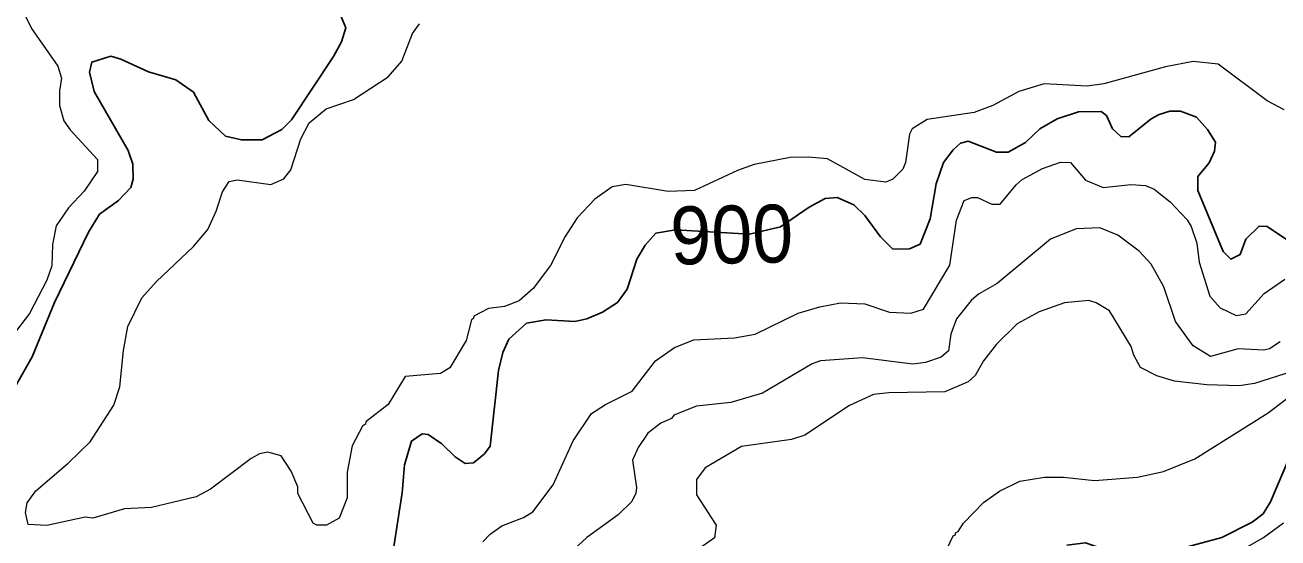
# Model space of a CAD drawing. Extents: x 598.3 to 623.2, y 6902.2 to 6930.1.
# Drawn here: x 617.225 to 618.956, y 6915.484 to 6916.193 of the extents above; entities that cross this region are included whole.
import ezdxf
from ezdxf.enums import TextEntityAlignment as Align

# ---------------------------------------------------------------- set-up
doc = ezdxf.new("R2010")
doc.units = 0
doc.header["$LTSCALE"] = 0.032
doc.layers.add('1', color=7, linetype='Continuous', lineweight=25)
doc.layers.add('2', color=7, linetype='Continuous', lineweight=13)
doc.layers.add('61', color=7, linetype='Continuous')

msp = doc.modelspace()

# ---------------------------------------------------------------- linework, layer by layer
at = {"layer": '1'}
for points in [[(617.2112, 6915.6929), (617.2344, 6915.7347), (617.2654, 6915.8095), (617.3126, 6915.907), (617.3277, 6915.9319), (617.3538, 6915.9509), (617.3711, 6915.9685), (617.3742, 6915.9802), (617.3738, 6916.0009), (617.3674, 6916.0197), (617.3202, 6916.1013), (617.3137, 6916.1281), (617.3172, 6916.1421), (617.3434, 6916.1501), (617.3569, 6916.1463), (617.3952, 6916.1288), (617.4333, 6916.1177), (617.4577, 6916.1005), (617.4785, 6916.0614), (617.5019, 6916.0394), (617.5237, 6916.0344), (617.5523, 6916.0344), (617.5796, 6916.0488), (617.5929, 6916.0621), (617.6509, 6916.1499), (617.6619, 6916.1702), (617.6679, 6916.1892), (617.6541, 6916.2225)], [(618.9716, 6915.8938), (618.9408, 6915.9147), (618.9296, 6915.9153), (618.9111, 6915.897), (618.9032, 6915.8759), (618.8907, 6915.8695), (618.8797, 6915.88), (618.8451, 6915.9643), (618.8451, 6915.9839), (618.8604, 6916.0028), (618.8677, 6916.0191), (618.8692, 6916.0313), (618.8582, 6916.0487), (618.843, 6916.066), (618.8208, 6916.074), (618.8062, 6916.074), (618.7914, 6916.0698), (618.7806, 6916.0637), (618.7494, 6916.0385), (618.7385, 6916.0393), (618.7269, 6916.0498), (618.7187, 6916.0683), (618.7112, 6916.0737), (618.68, 6916.0732), (618.6506, 6916.0634), (618.6265, 6916.0497), (618.6068, 6916.0307), (618.5828, 6916.0174), (618.5666, 6916.0174), (618.5275, 6916.0326), (618.5171, 6916.0299), (618.5071, 6916.0209), (618.4937, 6916.003), (618.4833, 6915.9739), (618.4752, 6915.9254), (618.4612, 6915.8903), (618.4468, 6915.8839), (618.4234, 6915.8836), (618.4065, 6915.9005), (618.3847, 6915.9297), (618.3697, 6915.9446), (618.3467, 6915.9549), (618.3303, 6915.9534), (618.308, 6915.9416), (618.2684, 6915.9142), (618.2256, 6915.9041), (618.1232, 6915.9102), (618.0963, 6915.9054), (618.0813, 6915.8891), (618.0701, 6915.8694), (618.0567, 6915.8282), (618.0431, 6915.8097), (618.0224, 6915.7962), (618.0008, 6915.7869), (617.9841, 6915.7835), (617.9446, 6915.7858), (617.9177, 6915.7811), (617.8932, 6915.7591), (617.8848, 6915.7406), (617.8789, 6915.7154), (617.8673, 6915.6108), (617.8596, 6915.6004), (617.8443, 6915.588), (617.8327, 6915.5868), (617.8188, 6915.5962), (617.8006, 6915.6144), (617.7817, 6915.6269), (617.7734, 6915.6279), (617.7588, 6915.6181), (617.7491, 6915.5854), (617.7458, 6915.5465), (617.7337, 6915.4688)], [(618.6637, 6915.4742), (618.6896, 6915.4774), (618.7217, 6915.4662), (618.7616, 6915.4605), (618.7997, 6915.4636), (618.8782, 6915.4846), (618.9198, 6915.5059), (618.9351, 6915.5174), (618.9453, 6915.5338), (618.9809, 6915.6173)]]:
    msp.add_lwpolyline(points, dxfattribs=at)
at = {"layer": '2'}
for points in [[(617.2245, 6916.2072), (617.2335, 6916.1887), (617.2702, 6916.1362), (617.2753, 6916.1198), (617.2723, 6916.1021), (617.2723, 6916.0819), (617.2785, 6916.0608), (617.2873, 6916.0485), (617.3248, 6916.0073), (617.3248, 6915.9909), (617.3064, 6915.9634), (617.2848, 6915.9407), (617.268, 6915.9156), (617.2626, 6915.89), (617.2617, 6915.8604), (617.2551, 6915.8407), (617.231, 6915.7946), (617.2084, 6915.7651)], [(617.3607, 6915.7431), (617.367, 6915.7764), (617.3862, 6915.8163), (617.4062, 6915.8387), (617.4575, 6915.8871), (617.4772, 6915.9108), (617.4889, 6915.9358), (617.4974, 6915.9626), (617.5069, 6915.9768), (617.5178, 6915.9793), (617.5644, 6915.9729), (617.5824, 6915.9804), (617.5921, 6915.9929), (617.6058, 6916.0359), (617.6172, 6916.058), (617.6406, 6916.0772), (617.6784, 6916.0905), (617.7263, 6916.1218), (617.7455, 6916.1433), (617.76, 6916.1815), (617.7696, 6916.195)], [(618.9642, 6916.0761), (618.9406, 6916.0885), (618.8729, 6916.1393), (618.8383, 6916.1428), (618.8, 6916.1356), (618.7152, 6916.112), (618.6919, 6916.1089), (618.6324, 6916.1119), (618.5974, 6916.1015), (618.5615, 6916.082), (618.5361, 6916.0724), (618.471, 6916.0626), (618.4503, 6916.0499), (618.4466, 6916.0426), (618.4411, 6916.0031), (618.4372, 6915.9941), (618.4235, 6915.9803), (618.4141, 6915.9762), (618.3847, 6915.9796), (618.3335, 6916.0084), (618.3065, 6916.0108), (618.2816, 6916.01), (618.2321, 6916.0005), (618.2088, 6915.9922), (618.1494, 6915.9646), (618.1131, 6915.9633), (618.0545, 6915.9728), (618.0359, 6915.9695), (618.0119, 6915.9524), (617.9877, 6915.9265), (617.9708, 6915.9008), (617.9507, 6915.8609), (617.9266, 6915.8291), (617.9074, 6915.8118), (617.8871, 6915.8041), (617.8649, 6915.8012), (617.8447, 6915.7907), (617.8444, 6915.7875), (617.8414, 6915.7857), (617.8343, 6915.7572), (617.8118, 6915.7192), (617.7989, 6915.7113), (617.7497, 6915.7071), (617.7263, 6915.6684), (617.6956, 6915.6448), (617.6953, 6915.6416), (617.6909, 6915.6386), (617.6766, 6915.6115), (617.6697, 6915.5751), (617.6696, 6915.5397), (617.6586, 6915.5113), (617.6412, 6915.5017), (617.628, 6915.5018), (617.6228, 6915.5043), (617.6017, 6915.5457), (617.6016, 6915.5546), (617.5926, 6915.5765), (617.5784, 6915.5978), (617.5603, 6915.6028), (617.5485, 6915.6004), (617.5372, 6915.5941), (617.4812, 6915.5514), (617.4614, 6915.5408), (617.3995, 6915.5262), (617.3621, 6915.5243), (617.3186, 6915.5115), (617.3078, 6915.513), (617.2548, 6915.5011), (617.2292, 6915.5025), (617.2252, 6915.5191), (617.2279, 6915.5324), (617.2397, 6915.5492), (617.2844, 6915.5875), (617.3147, 6915.617), (617.3475, 6915.6676), (617.3555, 6915.6929), (617.3607, 6915.7431)], [(618.2334, 6915.7657), (618.293, 6915.7947), (618.3227, 6915.8038), (618.3511, 6915.8093), (618.3848, 6915.8078), (618.4191, 6915.7964), (618.4482, 6915.7947), (618.4657, 6915.8004), (618.5023, 6915.8611), (618.5116, 6915.9237), (618.5222, 6915.9508), (618.5326, 6915.955), (618.5405, 6915.955), (618.5602, 6915.9454), (618.5718, 6915.9454), (618.5938, 6915.9724), (618.6024, 6915.9795), (618.6303, 6915.9949), (618.6554, 6916.0035), (618.6692, 6916.0034), (618.6897, 6915.9787), (618.7139, 6915.9688), (618.7523, 6915.9728), (618.7725, 6915.9712), (618.7844, 6915.9663), (618.8067, 6915.9489), (618.83, 6915.9239), (618.8357, 6915.9145), (618.8433, 6915.8917), (618.8466, 6915.8655), (618.8613, 6915.8185), (618.8759, 6915.8023), (618.8978, 6915.7916), (618.9114, 6915.794), (618.9365, 6915.8219), (618.9649, 6915.8418)], [(618.9586, 6915.7552), (618.9438, 6915.7454), (618.936, 6915.7438), (618.9007, 6915.7454), (618.8622, 6915.735), (618.8383, 6915.7497), (618.8141, 6915.7832), (618.798, 6915.8315), (618.7803, 6915.8627), (618.7639, 6915.8807), (618.7345, 6915.9027), (618.7095, 6915.9129), (618.677, 6915.9114), (618.6415, 6915.897), (618.5676, 6915.8357), (618.5418, 6915.8213), (618.5317, 6915.8125), (618.5114, 6915.7872), (618.5036, 6915.7658), (618.5004, 6915.7426), (618.4904, 6915.7341), (618.4686, 6915.7265), (618.451, 6915.7244), (618.3817, 6915.7333), (618.3238, 6915.7291), (618.3122, 6915.725), (618.2437, 6915.6842), (618.1998, 6915.6715), (618.1522, 6915.6661), (618.1212, 6915.6538)], [(618.6608, 6915.8094), (618.6259, 6915.7969), (618.5952, 6915.7803), (618.5668, 6915.7521), (618.5486, 6915.729), (618.5372, 6915.7089), (618.5277, 6915.7001), (618.4954, 6915.6863), (618.4182, 6915.6846), (618.3967, 6915.6822), (618.3637, 6915.667), (618.3022, 6915.6261), (618.2836, 6915.62), (618.2147, 6915.6107), (618.1642, 6915.581), (618.1522, 6915.5648), (618.1522, 6915.5439), (618.1796, 6915.5017), (618.1772, 6915.4841), (618.1584, 6915.4708)], [(618.9754, 6915.7142), (618.9231, 6915.6977), (618.902, 6915.6944), (618.8574, 6915.696), (618.8127, 6915.7009), (618.7881, 6915.7082), (618.7656, 6915.7197), (618.7563, 6915.7368), (618.7526, 6915.7489), (618.7228, 6915.7979), (618.7045, 6915.8092), (618.6945, 6915.8125), (618.6608, 6915.8094)], [(617.8574, 6915.4788), (617.8671, 6915.4894), (617.8832, 6915.5007), (617.9132, 6915.5125), (617.9263, 6915.5203), (617.9545, 6915.5573), (617.9818, 6915.6185), (618.0071, 6915.6561), (618.0264, 6915.6687), (618.0636, 6915.6871), (618.0957, 6915.7292), (618.1219, 6915.7472), (618.1488, 6915.7578), (618.2047, 6915.7606), (618.2334, 6915.7657)], [(618.5068, 6915.4871), (618.5099, 6915.4882), (618.5102, 6915.4913), (618.5139, 6915.493), (618.5214, 6915.5043), (618.5489, 6915.5332), (618.5709, 6915.5488), (618.5991, 6915.5626), (618.6329, 6915.5681), (618.6592, 6915.568), (618.702, 6915.5633), (618.7615, 6915.5681), (618.7975, 6915.5761), (618.8408, 6915.5934), (618.942, 6915.657), (619.0168, 6915.714)], [(618.1212, 6915.6538), (618.1176, 6915.6494), (618.103, 6915.643), (618.0851, 6915.629), (618.0719, 6915.6092), (618.064, 6915.5915), (618.0695, 6915.5538), (618.0686, 6915.546), (618.063, 6915.5345), (618.044, 6915.5159), (618.0009, 6915.4849), (617.9578, 6915.445)], [(618.8594, 6915.4408), (618.9355, 6915.4846), (618.9634, 6915.5051)], [(618.4928, 6915.457), (618.5068, 6915.4871)]]:
    msp.add_lwpolyline(points, dxfattribs=at)

# ---------------------------------------------------------------- texts
at = {"layer": '61', "width": 0.95}
msp.add_text('900', height=0.08, rotation=1.169, dxfattribs=at).set_placement((618.2018, 6915.8637), align=Align.CENTER)

doc.saveas('drawing.dxf')
